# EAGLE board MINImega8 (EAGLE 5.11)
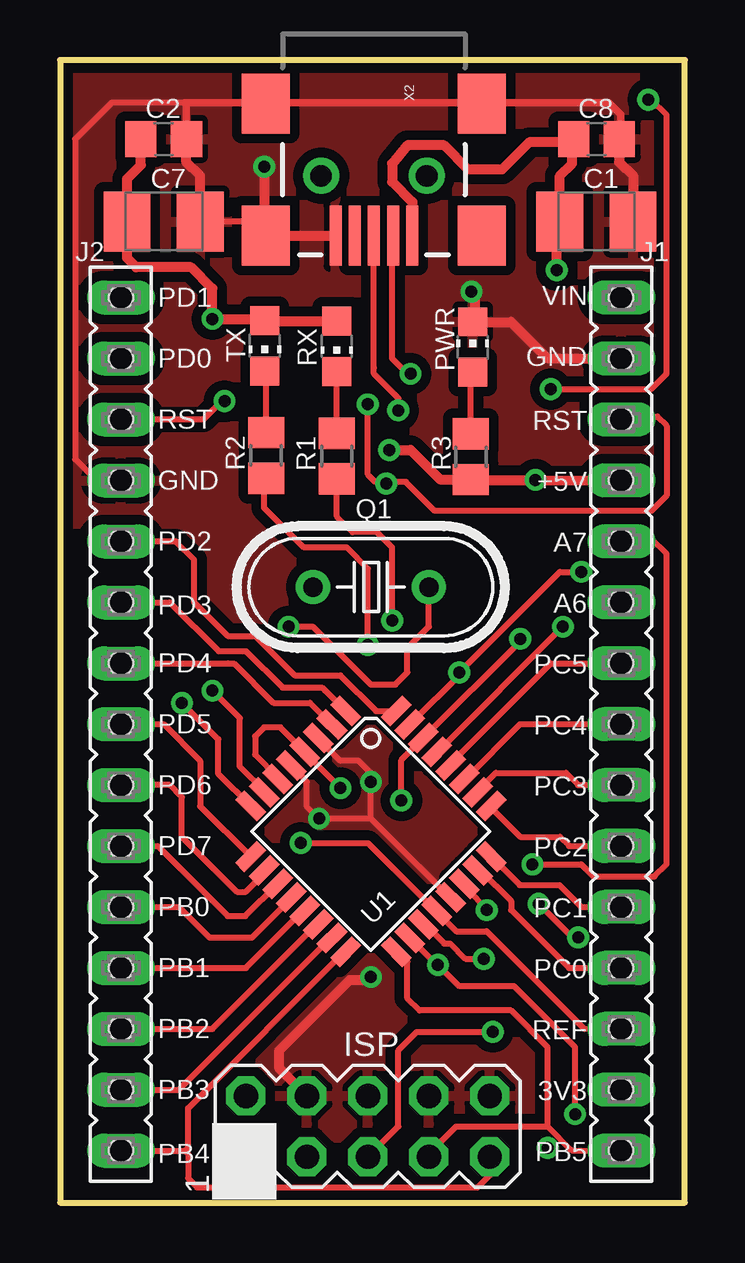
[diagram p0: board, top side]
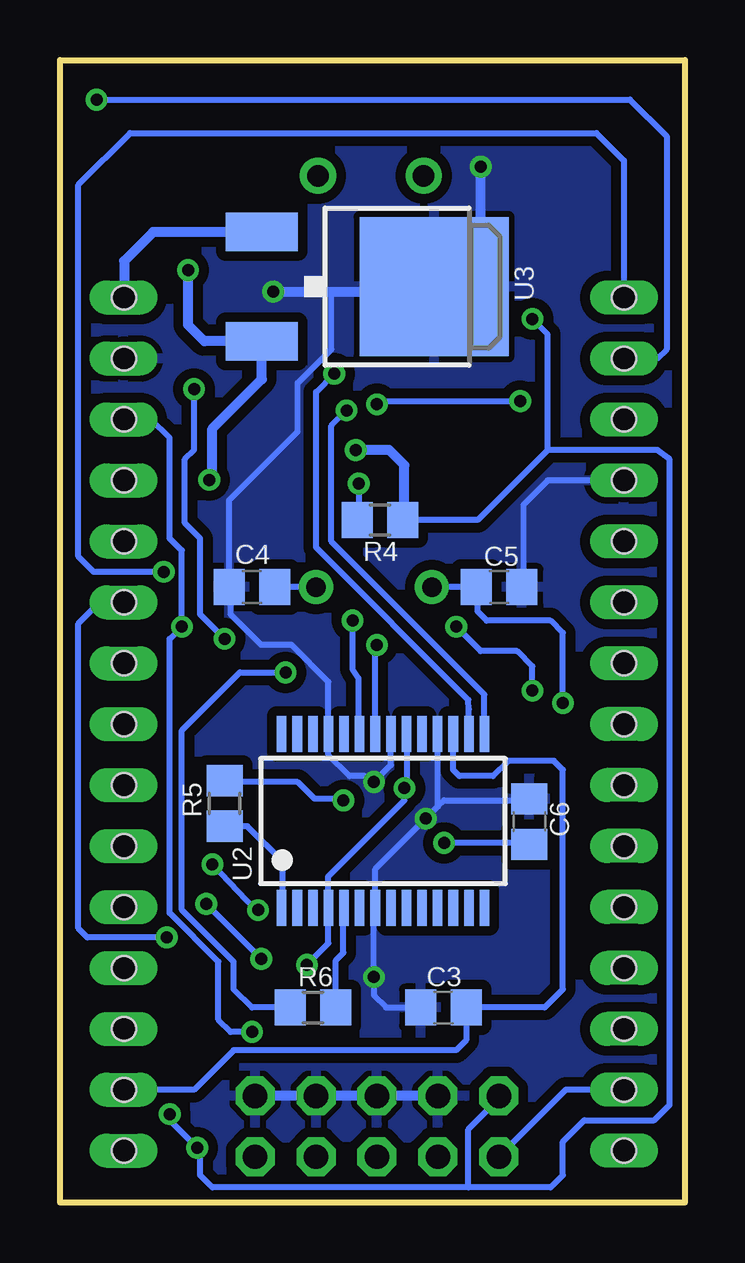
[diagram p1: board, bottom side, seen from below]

Size 26.04 x 47.62 mm. Coordinates in mm from the lower left corner, seen from the top.
Outline: 0,0 26.04,0 26.04,47.62 0,47.62 0,0
Copper layers (1*16): Top 0.035mm / dielectric 1.5mm / Bottom 0.035mm
Design rules "default *": minimum track width 8mil, minimum drill 16mil, track to track 8mil, track to pad 8mil, pad to pad 8mil, via to via 8mil, smd to smd 8mil, copper to edge 8mil, drill to drill 8mil, minimum pad ring 12mil, minimum via ring 8mil, stop-mask expansion 4mil, vias tented up to drill 18mil, thermal gap 10mil
Holes 1 mm at 2.54,2.16 2.54,4.7 2.54,7.24 2.54,9.78 2.54,12.32 2.54,14.86 2.54,17.4 2.54,19.94 2.54,22.48 2.54,25.02 2.54,27.56 2.54,30.1 2.54,32.64 2.54,35.18 2.54,37.72 23.37,2.16 23.37,4.7 23.37,7.24 23.37,9.78 23.37,12.32 23.37,14.86 23.37,17.4 23.37,19.94 23.37,22.48 23.37,25.02 23.37,27.56 23.37,30.1 23.37,32.64 23.37,35.18 23.37,37.72

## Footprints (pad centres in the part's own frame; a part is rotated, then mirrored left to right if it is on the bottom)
B/3528-21R = smd 1.95 x 2.5: + 1.525,0; - -1.525,0
C0805 = smd 1.3 x 1.5: 1 -0.95,0; 2 0.95,0
MA05-2 = drill 1.016 octagon: 1 -5.08,-1.27; 2 -5.08,1.27; 3 -2.54,-1.27; 4 -2.54,1.27; 5 0,-1.27; 6 0,1.27; 7 2.54,-1.27; 8 2.54,1.27; 9 5.08,-1.27; 10 5.08,1.27
FE15 = drill 0.813 long: 1 -17.78,0; 2 -15.24,0; 3 -12.7,0; 4 -10.16,0; 5 -7.62,0; 6 -5.08,0; 7 -2.54,0; 8 0,0; 9 2.54,0; 10 5.08,0; 11 7.62,0; 12 10.16,0; 13 12.7,0; 14 15.24,0; 15 17.78,0
CHIP-LED0805 = smd 1.2 x 1.2: A 0,-1.05; C 0,1.05
HC49U70 = drill 0.813 round: 1 -2.413,0; 2 2.413,0
R0805 = smd 1.3 x 1.5: 1 -0.95,0; 2 0.95,0
TQFP32-08 = smd 1.27 x 0.559: 1 -4.293,2.8; 2 -4.293,2; 3 -4.293,1.2; 4 -4.293,0.4; 5 -4.293,-0.4; 6 -4.293,-1.2; 7 -4.293,-2; 8 -4.293,-2.8; 17 4.293,-2.8; 18 4.293,-2; 19 4.293,-1.2; 20 4.293,-0.4; 21 4.293,0.4; 22 4.293,1.2; 23 4.293,2; 24 4.293,2.8 | smd 0.559 x 1.27: 9 -2.8,-4.293; 10 -2,-4.293; 11 -1.2,-4.293; 12 -0.4,-4.293; 13 0.4,-4.293; 14 1.2,-4.293; 15 2,-4.293; 16 2.8,-4.293; 25 2.8,4.293; 26 2,4.293; 27 1.2,4.293; 28 0.4,4.293; 29 -0.4,4.293; 30 -1.2,4.293; 31 -2,4.293; 32 -2.8,4.293
SSOP28 = smd 0.4 x 1.5: 1 -4.225,-3.625; 2 -3.575,-3.625; 3 -2.925,-3.625; 4 -2.275,-3.625; 5 -1.625,-3.625; 6 -0.975,-3.625; 7 -0.325,-3.625; 8 0.325,-3.625; 9 0.975,-3.625; 10 1.625,-3.625; 11 2.275,-3.625; 12 2.925,-3.625; 13 3.575,-3.625; 14 4.225,-3.625; 15 4.225,3.625; 16 3.575,3.625; 17 2.925,3.625; 18 2.275,3.625; 19 1.625,3.625; 20 0.975,3.625; 21 0.325,3.625; 22 -0.325,3.625; 23 -0.975,3.625; 24 -1.625,3.625; 25 -2.275,3.625; 26 -2.925,3.625; 27 -3.575,3.625; 28 -4.225,3.625
DPACK = smd 1.6 x 3: 1 -2.28,-4.8; 3 2.28,-4.8 | smd 5.8 x 6.2: 4 0,2.38
USB-MINIB-NOSTOP = smd 2.5 x 0.5: D+ 2.5,0; D- 2.5,0.8; GND 2.5,-1.6; ID 2.5,-0.8; VBUS 2.5,1.6 | smd 2.5 x 2: G1 -3,-4.5; G2 -3,4.5; G3 2.5,4.5; G4 2.5,-4.5 | drill 0.9 pad 0.8 round: H1 0,2.2 | drill 0.9 pad 0.787 round: H2 0,-2.2

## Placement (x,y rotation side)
C1  [B/3528-21R]  22.35,40.89 180 top
C2  100nF  [C0805]  4.32,44.32 0 top
C3  100nF  [C0805]  10.06,8.13 180 bottom
C4  22pF  [C0805]  18.03,25.65 180 bottom
C5  22pF  [C0805]  7.75,25.65 0 bottom
C6  100nF  [C0805]  6.48,15.88 90 bottom
C7  [B/3528-21R]  4.32,40.89 180 top
C8  100nF  [C0805]  22.35,44.32 0 top
ISP  [MA05-2]  12.83,3.17 0 top
J1  [FE15]  23.39,19.94 90 top
J2  [FE15]  2.54,19.94 270 top
PWR  [CHIP-LED0805]  17.2,35.66 0 top
Q1  [HC49U70]  12.95,25.65 180 top
R1  470  [R0805]  11.53,31.11 90 top
R2  470  [R0805]  8.59,31.14 90 top
R3  470  [R0805]  17.12,31.09 270 top
R4  1k  [R0805]  12.7,28.45 180 bottom
R5  1k  [R0805]  19.18,16.64 270 bottom
R6  1k  [R0805]  15.49,8.13 0 bottom
RX  [CHIP-LED0805]  11.53,35.69 180 top
TX  [CHIP-LED0805]  8.53,35.71 180 top
U1  MEGA8-AI  [TQFP32-08]  12.95,15.47 315 top
U2  FT232RL  [SSOP28]  12.57,15.9 0 bottom
U3  78M05  [DPACK]  12.83,38.18 270 bottom
X2  USB-SMD-NS  [USB-MINIB-NOSTOP]  13.08,42.8 270 top

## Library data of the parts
C1-C8 R1-R6 = rcl
ISP = con-lstb
J1 J2 = con-lsta
PWR RX TX = led
Q1 = crystal; OC_FARNELL: unknown; OC_NEWARK: unknown
U1 = atmel; MPN: ATMEGA8-16AU; OC_FARNELL: 9171371; OC_NEWARK: 73M8863
U2 = ftdichip; MPN: FT232RL; OC_FARNELL: 1146032; OC_NEWARK: 91K9918
U3 = v-reg
X2 = SparkFun

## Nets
+3V3: C3.1 J1.2 U2.17
+5V: C1.+ C2.1 C7.+ C8.1 ISP.2 J1.12 R3.2 R4.1 RX.A TX.A U1.4 U1.6 U1.18 U2.4 U2.20 U3.3 X2.VBUS
A6: J1.10 U1.19
A7: J1.11 U1.22
AREF: C6.1 J1.3 U1.20
GND: C1.- C2.2 C3.2 C4.2 C5.2 C6.2 C7.- C8.2 ISP.4 ISP.6 ISP.8 ISP.10 J1.14 J2.4 PWR.C U1.3 U1.5 U1.21 U2.7 U2.18 U2.21 U2.25 U3.4 X2.GND
N$5: PWR.A R3.1
N$28: R1.2 RX.C
N$29: R2.2 TX.C
N$31: U2.15 X2.D+
N$32: U2.16 X2.D-
N$37: R2.1 U2.22
N$38: R1.1 U2.23
N$40: C5.1 Q1.2 U1.8
N$41: C4.1 Q1.1 U1.7
PB0: J2.11 U1.12
PB1: J2.12 U1.13
PB2: J2.13 U1.14
PB3/MOSI: ISP.1 J2.14 U1.15
PB4/MISO: ISP.9 J2.15 U1.16
PB5/SCK: ISP.7 J1.1 U1.17
PC0/A0: J1.4 U1.23
PC1/A1: J1.5 U1.24
PC2/A2: J1.6 U1.25
PC3/A3: J1.7 U1.26
PC4/A4: J1.8 U1.27
PC5/A5: J1.9 U1.28
PD0/RX: J2.2 R5.1 U1.30
PD1/TX: J2.1 R6.1 U1.31
PD2: J2.5 U1.32
PD3: J2.6 U1.1
PD4: J2.7 U1.2
PD5: J2.8 U1.9
PD6: J2.9 U1.10
PD7: J2.10 U1.11
RESET: ISP.5 J1.13 J2.3 R4.2 U1.29
RX: R5.2 U2.1
TX: R6.2 U2.5
VIN: J1.15 U3.1

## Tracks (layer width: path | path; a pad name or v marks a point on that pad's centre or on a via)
+3V3
  Bottom 0.254: J1.2 20.45,4.7 18.8,6.35 9.53,6.35 9.11,6.77 C3.1 5.84,8.13 5.08,8.89 5.08,18.03 5.46,18.41 7.37,18.41 8,17.78 9.4,17.78 9.65,18.03 U2.17
+5V  (via drill 0.5 pad 0.61)
  Top 0.254: U1.6 9.07,17.73 8.13,18.67 8.13,19.43 8.51,19.81 9.18,19.81 U1.4 10.2,18.75 v11.68,17.27 | U1.18 15.69,9.91 v15.75,9.91 16.64,9.02 18.92,9.02 21.46,6.48 v21.46,3.68 | v20.32,2.29 20.29,2.26 | RX.A 11.43,36.84 | 8.69,36.74 TX.A 8.47,36.83 | C8.1 21.34,44.26 21.34,43.82 21.21,44.2 | C7.+ | 20.7,41.02 C1.+ | R3.2 17.14,30.12
  Top 0.406: 8.69,36.74 RX.A | J1.12 v19.81,30.12 17.14,30.12 | 8.47,36.83 v6.35,36.83 6.35,38.1 5.46,38.99 3.17,38.99 2.79,39.37 C7.+ | C1.+ 20.83,42.8 21.34,43.31 21.34,43.82 | C2.1 3.37,43.25 2.79,42.67 C7.+ | v20.7,38.86 20.7,41.02 | R3.2 15.83,30.14 14.61,31.37 v13.72,31.37 | X2.VBUS 14.68,41.71 13.84,42.55 13.84,43.31 14.48,44.07 16,44.07 17.02,43.05 18.41,43.05 19.56,44.2 21.21,44.2
  Bottom 0.254: v15.75,9.91 14.85,10.81 U2.4 14.86,13.59 11.68,16.76 v11.68,17.27 11.56,17.4 11.56,19.48 U2.20 | v21.46,3.68 21.46,3.43 v20.32,2.29 20.19,2.16 20.19,1.14 19.68,0.64 9.02,0.64 | v19.81,30.12 19.68,30.25 | 5.71,31.37 8.64,28.45 R4.1 11.68,28.51 | 5.71,31.37 1.14,31.37 0.64,30.99 0.64,4.06 1.27,3.43 4.19,3.43 5.08,2.54 5.08,1.14 5.59,0.64 9.02,0.64 | 5.71,31.37 5.71,36.2 v6.35,36.83 | ISP.2 7.75,4.32 9.02,3.05 9.02,0.64
  Bottom 0.406: v20.7,38.86 20.7,36.58 20.02,35.9 U3.3 17.63,34.32 19.68,32.26 19.68,30.25 | v13.72,31.37 12.32,31.37 11.68,30.73 11.68,28.51
A6  (via drill 0.5 pad 0.61)
  Top 0.254: U1.19 15.21,11.59 16,10.79 16.26,10.79 16.89,10.16 v17.65,10.16 | v21.59,11.05 21.34,11.05 v19.94,12.45
  Bottom 0.254: J1.10 24.36,25.04 25.27,24.13 25.27,11.43 24.89,11.05 v21.59,11.05 | v17.65,10.16 v19.94,12.45
A7  (via drill 0.5 pad 0.61)
  Top 0.254: U1.22 16.84,13.26 v17.78,12.19 | v19.68,14.1 21.72,14.1 22.22,13.59 24.77,13.59 25.27,14.1 25.27,27.05 24.64,27.69 23.49,27.69 J1.11
  Bottom 0.254: v17.78,12.19 17.91,12.19 v19.68,14.1
AREF  (via drill 0.5 pad 0.61)
  Top 0.254: J1.3 22.37,7.26 21.84,7.24 17.78,11.3 16.51,11.3 15.71,12.11 U1.20 15.66,12.15 12.83,14.99 v10.03,14.99
  Bottom 0.254: v10.03,14.99 6.54,14.99 C6.1
GND  (via drill 0.5, 0.5 pad 0.61)
  Top 0.254: U1.21 16.24,12.72 12.95,16 | U1.5 9.71,18.22 10.29,17.53 10.29,16.51 v10.8,16 12.95,16 | U1.3 10.77,19.33 11.68,18.41 12.45,18.41 12.95,17.91 v12.95,17.53 12.95,16 | 12.83,9.27 v12.95,9.4 | 23.37,44.39 C8.2 | 23.88,41.15 C1.- | PWR.C 17.27,36.79 | C7.- 8.41,40.89 9,40.3 X2.GND | 17.02,37.97 17.17,38 | 17.02,37.97 16.89,38.1 | v17.14,37.97 17.02,37.97 | J2.4 1.52,30.1 0.64,30.99 0.64,44.32 2.16,45.85 5.21,45.85 5.27,45.79 | 9.06,40.3 9.02,40.26 8.51,39.88
  Top 0.305: 23.37,44.39 23.37,45.34 22.86,45.85 5.21,45.85 | C2.2 5.27,45.79
  Top 0.406: 12.83,9.27 12.07,9.27 9.14,6.35 9.14,5.59 ISP.4 | C8.2 23.3,43.37 23.88,42.8 23.88,41.15 | J1.14 20.29,35.2 18.8,36.7 PWR.C | C2.2 5.27,43.37 5.84,42.8 C7.- | 17.02,37.97 17.27,37.72 17.27,36.79 | 9.06,40.3 X2.GND | v8.51,43.18 8.51,39.88
  Bottom 0.254: C3.2 12.45,8.13 12.95,8.64 v12.95,9.4 12.95,12.22 U2.7 12.9,13.9 v10.8,16 10.29,16.51 | C6.2 6.29,16.76 10.03,16.76 10.29,16.51 | U2.18 10.3,16.52 10.29,16.51 | 12.19,19.58 U2.21 12.25,18.23 v12.95,17.53 13.34,17.78 13.97,17.78 14.85,18.66 U2.25 14.85,21.71 16.38,23.24 17.65,23.24 18.92,24.51 18.92,25.59 C4.2 18.98,29.28 16.13,32.13 16.13,34.16 14.73,35.56 14.73,37.97 v17.14,37.97 | 10.65,37.97 U3.4 10.14,38.48 8.64,38.48 8.51,38.61 | 6.73,26.16 6.73,25.72 C5.2 6.8,26.1 6.73,26.16 | 6.73,26.16 6.73,29.08 5.71,30.1 J2.4
  Bottom 0.406: v17.14,37.97 10.65,37.97 | ISP.4 ISP.6 ISP.8 ISP.10 | 8.51,38.61 v8.51,43.18
  pour Bottom (isolate 0.406): 0.25,0 25.78,0 25.78,47.62 0.13,47.75
  pour Top (isolate 0.406): 0,-0.13 25.78,0 25.78,47.75 0.13,47.75
N$5
  Top 0.254: R3.1 17.12,34.54 PWR.A
N$28
  Top 0.254: R1.2 RX.C
N$29
  Top 0.254: R2.2 8.59,34.61 TX.C
N$31  (via drill 0.5 pad 0.61)
  Top 0.254: v14.1,33.02 14.1,33.53 13.08,34.54 13.08,34.8 X2.D+
  Bottom 0.254: U2.15 8.35,21.18 14.73,27.56 14.73,32.38 v14.1,33.02
N$32  (via drill 0.5)
  Top 0.254: v14.61,34.54 14.48,34.54 13.84,35.18 13.84,40.26 X2.D-
  Bottom 0.254: U2.16 9,20.55 9.02,20.95 15.37,27.3 15.37,33.78 v14.61,34.54
N$37  (via drill 0.5 pad 0.61)
  Top 0.254: v12.83,23.24 12.83,26.42 11.94,27.3 10.16,27.3 8.51,28.96 8.51,30.11 R2.1
  Bottom 0.254: U2.22 12.9,23.04 v12.83,23.24
N$38  (via drill 0.5 pad 0.61)
  Top 0.254: R1.1 11.53,28.6 12.19,27.94 13.21,27.94 13.84,27.3 v13.84,24.26
  Bottom 0.254: v13.84,24.26 13.84,22.22 13.59,21.84 13.59,19.57 U2.23
N$40  (via drill 0.5 pad 0.61)
  Top 0.254: U1.8 6.6,17.86 6.6,19.3 v5.08,20.83
  Bottom 0.254: v5.08,20.83 5.08,23.75 5.59,24.26 8.25,24.26 8.64,24.64 8.64,25.59 C5.1 Q1.2
N$41  (via drill 0.5 pad 0.61)
  Top 0.254: U1.7 8.5,17.15 7.49,18.16 7.49,20.19 v6.35,21.34 | v9.53,24 10.54,24 12.95,21.59 13.97,21.59 14.48,22.1 14.48,23.11 15.37,24 Q1.1
  Bottom 0.254: 6.35,21.46 v6.35,21.34 6.35,22.35 6.99,22.99 8.51,22.99 v9.53,24 | Q1.1 C4.1
PB0
  Top 0.254: U1.12 9.64,12.68 8,11.05 6.22,11.05 4.95,12.32 J2.11
PB1
  Top 0.254: U1.13 10.12,12.15 7.75,9.78 J2.12
PB2
  Top 0.254: U1.14 10.7,11.59 6.35,7.24 J2.13
PB3/MOSI
  Top 0.254: U1.15 11.28,11.02 4.95,4.7 J2.14
  Bottom 0.254: J2.14 4.95,4.7 ISP.1
PB4/MISO
  Top 0.254: U1.16 11.85,10.46 5.33,3.94 5.33,2.29 5.21,2.16 | J2.15 5.21,2.16 | ISP.9 17.91,1.14 17.4,0.64 5.71,0.64 5.33,1.02 5.33,2.03 5.21,2.16
PB5/SCK
  Top 0.254: U1.17 14.48,10.03 14.48,8.51 14.99,8 18.8,8 20.32,6.48 20.32,3.17 | J1.1 21.31,2.18 20.32,3.17 | ISP.7 15.37,2.03 16.51,3.17 20.32,3.17
PC0/A0
  Top 0.254: U1.23 17.52,13.85 18.8,12.57 18.8,12.19 21.21,9.78 J1.4
PC1/A1
  Top 0.254: J1.5 21.72,12.32 20.8,13.23 19.15,13.23 U1.24
PC2/A2
  Top 0.254: U1.25 17.97,16.45 19.18,15.24 20.83,15.24 21.21,14.86 J1.6
PC3/A3
  Top 0.254: U1.26 17.4,17.15 18.16,17.91 21.08,17.91 21.59,17.4 J1.7
PC4/A4
  Top 0.254: U1.27 16.9,17.66 19.18,19.94 J1.8
PC5/A5
  Top 0.254: U1.28 16.27,18.3 20.45,22.48 J1.9
PD0/RX  (via drill 0.5 pad 0.61)
  Top 0.254: v14.22,16.76 14.22,18.44 U1.30 | U1.30 15.16,19.36 | v24.51,45.97 24.64,45.97 25.27,45.34 25.27,34.54 24.64,33.91 v20.45,33.91 | v19.18,23.5 19.18,23.39 U1.30
  Bottom 0.254: R5.1 19.18,17.4 19.05,17.53 16.13,17.53 15.43,16.82 14.29,16.82 v14.22,16.76 | J2.2 1.14,35.18 0.76,35.56 0.76,44.45 2.29,45.97 v24.51,45.97 | v20.45,33.91 20.45,31.37 20.83,30.99 20.83,28.32 20.19,27.69 20.19,24.51 v19.18,23.5
PD1/TX  (via drill 0.5 pad 0.61)
  Top 0.254: U1.31 16.75,22.1 v16.64,22.1 20.83,26.29 v21.72,26.29
  Bottom 0.254: R6.1 18.03,8.13 18.8,8.89 18.8,10.03 20.95,12.19 20.95,19.68 18.54,22.1 v16.64,22.1 | J2.1 2.54,43.43 3.68,44.58 23.11,44.58 25.27,42.42 25.27,26.92 24.64,26.29 v21.72,26.29
PD2
  Top 0.254: U1.32 13.17,20.49 11.68,21.97 9.78,21.97 8.13,23.62 6.99,23.62 5.59,25.02 5.59,26.8 4.83,27.56 J2.5
PD3
  Top 0.254: J2.6 4.57,25.02 6.61,22.99 7.75,22.99 9.27,21.46 10.92,21.46 11.05,21.34 U1.1
PD4
  Top 0.254: J2.7 7,22.48 7.25,22.47 8.89,20.83 10.41,20.83 U1.2
PD5
  Top 0.254: J2.8 4.32,19.94 5.84,18.41 5.84,16.51 U1.9
PD6
  Top 0.254: U1.10 8.5,13.71 7.75,12.95 7.37,12.95 5.08,15.24 5.08,16.89 4.57,17.4 J2.9
PD7
  Top 0.254: J2.10 4.06,14.86 6.99,11.94 7.72,11.94 U1.11
RESET  (via drill 0.5 pad 0.61)
  Top 0.254: U1.29 15.74,18.79 v20.95,24 21.08,24.13 | v18.03,7.11 14.86,7.11 14.1,6.35 14.1,3.17 ISP.5 | v12.83,33.27 12.83,30.35 13.14,30.04 13.52,30.04 | v6.86,33.4 6.73,33.4 5.97,32.64 J2.3 | 13.52,30.04 14.41,30.04 15.62,28.83 24.64,28.83 25.27,29.46 25.27,32.38 24.89,32.77 23.49,32.77 J1.13 | 13.52,30.04 v13.59,29.97
  Bottom 0.254: v18.03,7.11 18.92,7.11 19.43,7.62 19.43,10.03 21.46,12.06 21.46,23.5 v20.95,24 20.95,27.18 21.46,27.69 21.46,31.88 22.25,32.66 J1.13 | v12.83,33.27 12.57,33.4 v6.86,33.4 | v13.59,29.97 13.59,28.51 R4.2
RX
  Bottom 0.254: R5.2 18.23,15.69 16.76,14.22 16.76,12.31 U2.1
TX
  Bottom 0.254: R6.2 14.54,10.09 14.22,10.41 14.22,12.25 U2.5
VIN
  Bottom 0.254: 23.37,37.77 J1.15
  Bottom 0.406: U3.1 22.15,40.46 23.37,39.24 23.37,37.77

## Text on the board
tNames: VIN | PD1 | GND | PD0 | RST | RST | +5V | GND | A7 | PD2 | A6 | PD3 | PC5 | PD4 | PD5 | PC4 | PC3 | PD6 | PD7 | PC2 | PC1 | PB0 | PB1 | PC0 | REF | PB2 | 3V3 | PB3 | PB5 | PB4 | 1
